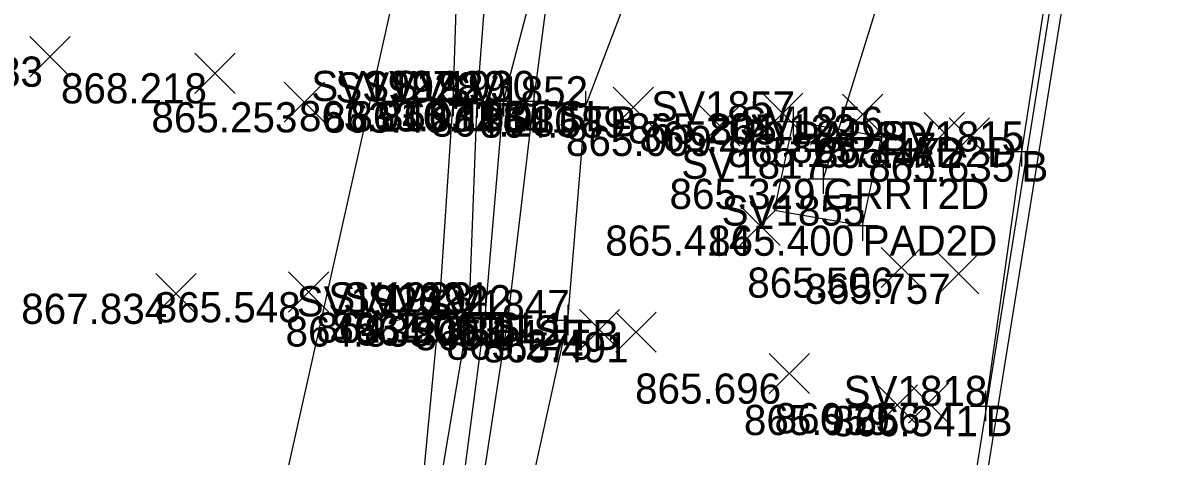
# Model space of a CAD drawing. Extents: x 2228183 to 2230895, y 679226 to 682223.
# Drawn here: x 2228233.78 to 2228271.79, y 680400.51 to 680414.86 of the extents above; entities that cross this region are included whole.
import ezdxf

# ---------------------------------------------------------------- set-up
doc = ezdxf.new("R2010")
doc.units = 0
for name, color, linetype in [('DR_X_Ditch', 7, 'Continuous'), ('PV_X_EOP', 7, 'Continuous'), ('PV_X_Shoulder_Aggregate', 7, 'Continuous'), ('RD_X_Concrete_Pad', 7, 'Continuous'), ('RD_X_GR_Rt', 7, 'Continuous'), ('SC_Scratch1', 7, 'Continuous'), ('SV_P_Control_Cells_Set', 7, 'Continuous'), ('SV_X_Break_Lines', 7, 'Continuous'), ('SV_X_Random_Point', 7, 'Continuous'), ('SV_X_Shot_Marker', 7, 'Continuous'), ('SV_X_Text_Comment', 7, 'Continuous'), ('SV_X_Toe_of_Slope', 7, 'Continuous'), ('SV_X_Top_of_Bank', 7, 'Continuous'), ('VG_X_Tree_Line_Rt', 7, 'Continuous')]:
    doc.layers.add(name, color=color, linetype=linetype)

msp = doc.modelspace()

# ---------------------------------------------------------------- linework, layer by layer
at = {"layer": 'DR_X_Ditch'}
msp.add_lwpolyline([(2228248.152, 680398.096), (2228249.095, 680405.268), (2228249.691, 680412.267), (2228250.738, 680416.294), (2228251.182, 680418.776), (2228251.754, 680424.586), (2228252.425, 680433.411), (2228253.413, 680441.336), (2228254.696, 680448.568), (2228253.869, 680453.653), (2228253.021, 680456.333), (2228253.924, 680458.912), (2228254.395, 680462.481), (2228255.204, 680465.484), (2228255.304, 680468.353), (2228255.892, 680471.795), (2228254.699, 680480.343), (2228253.82, 680482.578)], dxfattribs=at)
at = {"layer": 'PV_X_EOP'}
msp.add_lwpolyline([(2228252.395, 680193.158), (2228252.017, 680217.928), (2228252.166, 680243.969), (2228252.969, 680269.118), (2228254.41, 680295.326), (2228256.289, 680320.959), (2228258.609, 680345.957), (2228261.353, 680370.084), (2228265.081, 680396.038), (2228268.964, 680420.227), (2228273.571, 680445.935), (2228278.026, 680470.103), (2228282.912, 680494.405), (2228287.764, 680519.213), (2228292.491, 680542.983), (2228297.123, 680567.244), (2228301.725, 680591.365), (2228306.593, 680616.395), (2228311.35, 680641.501), (2228316.271, 680666.166), (2228321.17, 680690.642)], dxfattribs=at)
at = {"layer": 'PV_X_Shoulder_Aggregate'}
msp.add_lwpolyline([(2228251.688, 680193.163), (2228251.4, 680217.895), (2228251.524, 680243.996), (2228252.468, 680269.192), (2228253.879, 680295.388), (2228256.006, 680320.988), (2228258.289, 680346.01), (2228261.054, 680370.168), (2228264.719, 680396.078), (2228268.579, 680420.338), (2228273.034, 680446.093), (2228277.679, 680470.182), (2228282.388, 680494.533), (2228287.18, 680519.364), (2228291.91, 680543.114), (2228296.422, 680567.366), (2228298.906, 680579.954), (2228299.502, 680580.4), (2228300.213, 680585.238), (2228301.248, 680591.351), (2228306.286, 680616.474), (2228310.79, 680641.597), (2228315.628, 680666.277), (2228320.418, 680690.758)], dxfattribs=at)
at = {"layer": 'RD_X_Concrete_Pad'}
for p, q in [((2228259.272, 680411.599), (2228258.643, 680408.663)), ((2228258.643, 680408.663), (2228261.577, 680408.149))]:
    msp.add_line(p, q, dxfattribs=at)
msp.add_lwpolyline([(2228261.577, 680408.149), (2228262.206, 680411.085), (2228259.272, 680411.599)], dxfattribs=at)
at = {"layer": 'RD_X_GR_Rt'}
msp.add_lwpolyline([(2228317.277, 680691.491), (2228312.595, 680666.948), (2228307.846, 680642.212), (2228302.988, 680616.983), (2228299.878, 680601.719), (2228297.761, 680591.905), (2228295.954, 680582.306), (2228293.417, 680567.926), (2228288.785, 680543.533), (2228284.091, 680519.921), (2228279.274, 680495.191), (2228277.122, 680484.488), (2228274.573, 680472.619), (2228272.345, 680459.942), (2228269.701, 680446.744), (2228267.226, 680435.025), (2228263.818, 680421.121), (2228260.268, 680409.699)], dxfattribs=at)
at = {"layer": 'SV_X_Break_Lines'}
msp.add_lwpolyline([(2228320.273, 680690.8), (2228315.504, 680666.348), (2228310.738, 680641.634), (2228307.941, 680626.405), (2228307.393, 680623.472), (2228306.032, 680616.453), (2228303.053, 680601.155), (2228302.136, 680596.655), (2228301.06, 680591.437), (2228300.056, 680585.377), (2228299.678, 680583.167), (2228299.406, 680580.537), (2228298.77, 680580.019), (2228296.305, 680567.394), (2228291.772, 680543.248), (2228287.045, 680519.362), (2228285.465, 680511.012), (2228284.573, 680506.414), (2228282.283, 680494.649), (2228277.562, 680470.257), (2228272.956, 680446.158), (2228268.352, 680420.353), (2228266.832, 680410.603), (2228265.647, 680402.172)], dxfattribs=at)
at = {"layer": 'SV_X_Random_Point'}
for p, q in [((2228234.002, 680413.082), (2228235.336, 680414.417)), ((2228234.002, 680414.417), (2228235.336, 680413.082)), ((2228239.469, 680412.529), (2228240.803, 680413.864)), ((2228239.469, 680413.864), (2228240.803, 680412.529)), ((2228242.427, 680411.57), (2228243.761, 680412.905)), ((2228242.427, 680412.905), (2228243.761, 680411.57)), ((2228253.323, 680411.395), (2228254.657, 680412.73)), ((2228253.323, 680412.73), (2228254.657, 680411.395)), ((2228258.261, 680411.202), (2228259.595, 680412.537)), ((2228258.261, 680412.537), (2228259.595, 680411.202)), ((2228260.911, 680411.17), (2228262.245, 680412.505)), ((2228260.911, 680412.505), (2228262.245, 680411.17)), ((2228256.172, 680410.788), (2228257.506, 680412.123)), ((2228256.172, 680412.123), (2228257.506, 680410.788)), ((2228263.614, 680410.559), (2228264.948, 680411.894)), ((2228263.614, 680411.894), (2228264.948, 680410.559)), ((2228264.44, 680410.389), (2228265.774, 680411.724)), ((2228264.44, 680411.724), (2228265.774, 680410.389)), ((2228257.512, 680407.485), (2228258.846, 680408.82)), ((2228257.512, 680408.82), (2228258.846, 680407.485)), ((2228262.195, 680406.093), (2228263.529, 680407.428)), ((2228262.195, 680407.428), (2228263.529, 680406.093)), ((2228264.086, 680405.889), (2228265.42, 680407.224)), ((2228264.086, 680407.224), (2228265.42, 680405.889)), ((2228238.175, 680405.226), (2228239.509, 680406.561)), ((2228238.175, 680406.561), (2228239.509, 680405.226)), ((2228242.571, 680405.277), (2228243.905, 680406.612)), ((2228242.571, 680406.612), (2228243.905, 680405.277)), ((2228252.199, 680404.037), (2228253.533, 680405.372)), ((2228252.199, 680405.372), (2228253.533, 680404.037)), ((2228253.41, 680403.951), (2228254.744, 680405.286)), ((2228253.41, 680405.286), (2228254.744, 680403.951)), ((2228258.481, 680402.582), (2228259.815, 680403.917)), ((2228258.481, 680403.917), (2228259.815, 680402.582)), ((2228262.063, 680401.542), (2228263.397, 680402.877)), ((2228262.063, 680402.877), (2228263.397, 680401.542)), ((2228263.099, 680401.602), (2228264.433, 680402.937)), ((2228263.099, 680402.937), (2228264.433, 680401.602))]:
    msp.add_line(p, q, dxfattribs=at)
at = {"layer": 'SV_X_Shot_Marker'}
for p, q in [((2228248.019, 680412.774), (2228248.019, 680411.774)), ((2228248.818, 680412.727), (2228248.818, 680411.727)), ((2228249.691, 680412.767), (2228249.691, 680411.767)), ((2228250.692, 680412.774), (2228250.692, 680411.774)), ((2228252.399, 680412.597), (2228252.399, 680411.597)), ((2228247.519, 680412.274), (2228248.519, 680412.274)), ((2228248.019, 680412.274), (2228248.019, 680412.274)), ((2228248.318, 680412.227), (2228249.318, 680412.227)), ((2228248.818, 680412.227), (2228248.818, 680412.227)), ((2228249.191, 680412.267), (2228250.191, 680412.267)), ((2228249.691, 680412.267), (2228249.691, 680412.267)), ((2228250.192, 680412.274), (2228251.192, 680412.274)), ((2228250.692, 680412.274), (2228250.692, 680412.274)), ((2228251.899, 680412.097), (2228252.899, 680412.097)), ((2228252.399, 680412.097), (2228252.399, 680412.097)), ((2228259.272, 680412.099), (2228259.272, 680411.099)), ((2228258.772, 680411.599), (2228259.772, 680411.599)), ((2228259.272, 680411.599), (2228259.272, 680411.599)), ((2228262.206, 680411.585), (2228262.206, 680410.585)), ((2228261.706, 680411.085), (2228262.706, 680411.085)), ((2228262.206, 680411.085), (2228262.206, 680411.085)), ((2228266.832, 680411.103), (2228266.832, 680410.103)), ((2228266.332, 680410.603), (2228267.332, 680410.603)), ((2228266.832, 680410.603), (2228266.832, 680410.603)), ((2228260.268, 680410.199), (2228260.268, 680409.199)), ((2228259.768, 680409.699), (2228260.768, 680409.699)), ((2228260.268, 680409.699), (2228260.268, 680409.699)), ((2228261.577, 680408.649), (2228261.577, 680407.649)), ((2228261.077, 680408.149), (2228262.077, 680408.149)), ((2228261.577, 680408.149), (2228261.577, 680408.149)), ((2228247.542, 680405.642), (2228247.542, 680404.642)), ((2228248.549, 680405.769), (2228248.549, 680404.769)), ((2228249.095, 680405.768), (2228249.095, 680404.768)), ((2228249.858, 680405.677), (2228249.858, 680404.677)), ((2228248.049, 680405.269), (2228249.049, 680405.269)), ((2228248.549, 680405.269), (2228248.549, 680405.269)), ((2228248.595, 680405.268), (2228249.595, 680405.268)), ((2228249.095, 680405.268), (2228249.095, 680405.268)), ((2228251.813, 680405.52), (2228251.813, 680404.52)), ((2228247.042, 680405.142), (2228248.042, 680405.142)), ((2228247.542, 680405.142), (2228247.542, 680405.142)), ((2228249.358, 680405.177), (2228250.358, 680405.177)), ((2228249.858, 680405.177), (2228249.858, 680405.177)), ((2228251.313, 680405.02), (2228252.313, 680405.02)), ((2228251.813, 680405.02), (2228251.813, 680405.02)), ((2228265.647, 680402.672), (2228265.647, 680401.672)), ((2228265.147, 680402.172), (2228266.147, 680402.172)), ((2228265.647, 680402.172), (2228265.647, 680402.172))]:
    msp.add_line(p, q, dxfattribs=at)
at = {"layer": 'SV_X_Toe_of_Slope'}
for points in [[(2228247.363, 680398.195), (2228248.549, 680405.269), (2228248.818, 680412.227), (2228249.327, 680418.887), (2228250.556, 680424.555), (2228251.157, 680433.567), (2228252.542, 680441.162), (2228253.839, 680448.589), (2228253.231, 680453.1), (2228252.107, 680454.105), (2228250.987, 680456.203), (2228252.313, 680459.504), (2228253.331, 680462.687), (2228254.374, 680464.819), (2228254.89, 680468.476), (2228255.601, 680471.521), (2228254.065, 680480.323), (2228253.345, 680482.191)], [(2228248.769, 680398.124), (2228249.858, 680405.177), (2228250.692, 680412.274), (2228251.23, 680416.422), (2228252.326, 680418.965), (2228253.526, 680423.926), (2228253.811, 680432.797), (2228253.924, 680435.141), (2228254.135, 680441.28), (2228255.741, 680448.336), (2228254.458, 680453.857), (2228254.543, 680454.732), (2228254.934, 680456.198), (2228255.832, 680458.437), (2228255.885, 680462.309), (2228256.037, 680464.674), (2228255.856, 680468.365), (2228256.292, 680472.05), (2228254.247, 680482.064)]]:
    msp.add_lwpolyline(points, dxfattribs=at)
at = {"layer": 'SV_X_Top_of_Bank'}
for points in [[(2228250.307, 680398.124), (2228251.813, 680405.02), (2228252.399, 680412.097), (2228254.905, 680418.699), (2228255.946, 680423.789), (2228256.296, 680434.591), (2228257.527, 680440.797), (2228257.898, 680448.164), (2228256.801, 680454.49), (2228258.019, 680458.203), (2228257.686, 680462.292), (2228256.963, 680468.691), (2228257.054, 680472.414), (2228255.862, 680480.443), (2228255.026, 680481.727), (2228254.275, 680482.126)], [(2228246.89, 680398.302), (2228247.542, 680405.142), (2228248.019, 680412.274), (2228248.247, 680419.019), (2228247.645, 680424.706), (2228248.424, 680434.173), (2228248.473, 680441.514)]]:
    msp.add_lwpolyline(points, dxfattribs=at)
at = {"layer": 'VG_X_Tree_Line_Rt'}
msp.add_lwpolyline([(2228242.224, 680398.608), (2228254.757, 680454.617), (2228285.377, 680608.953), (2228295.459, 680686.843), (2228290.96, 680699.609), (2228297.38, 680721.363), (2228313.146, 680792.869)], dxfattribs=at)

# ---------------------------------------------------------------- texts
at = {"layer": 'SC_Scratch1'}
for s, p in [('869.183', (2228229.605, 680412.749)), ('868.218', (2228235.036, 680412.196)), ('865.253', (2228238.03, 680411.237)), ('863.916', (2228242.915, 680411.274)), ('863.407', (2228243.722, 680411.227)), ('863.032', (2228244.618, 680411.267)), ('863.193', (2228245.628, 680411.274)), ('864.280', (2228247.285, 680411.097)), ('864.589', (2228248.906, 680411.062)), ('865.204', (2228253.806, 680410.869)), ('865.122', (2228256.505, 680410.837)), ('865.009', (2228251.755, 680410.455)), ('865.219', (2228254.188, 680410.599)), ('865.157', (2228257.11, 680410.085)), ('865.217', (2228259.185, 680410.226)), ('865.472', (2228260.034, 680410.056)), ('865.635', (2228261.762, 680409.603)), ('865.329', (2228255.184, 680408.699)), ('865.414', (2228253.057, 680407.152)), ('865.400', (2228256.463, 680407.149)), ('865.506', (2228257.758, 680405.76)), ('865.757', (2228259.657, 680405.556)), ('867.834', (2228233.72, 680404.893)), ('865.548', (2228238.138, 680404.944)), ('864.113', (2228243.485, 680404.269)), ('863.906', (2228243.991, 680404.268)), ('864.835', (2228242.472, 680404.142)), ('864.003', (2228244.794, 680404.177)), ('865.042', (2228246.74, 680404.02)), ('865.275', (2228247.796, 680403.704)), ('865.491', (2228248.995, 680403.618)), ('865.696', (2228254.044, 680402.249)), ('865.959', (2228257.646, 680401.209)), ('866.256', (2228258.662, 680401.269)), ('866.341', (2228260.565, 680401.172))]:
    msp.add_text(s, height=1, dxfattribs=at).set_placement(p)
at = {"layer": 'SV_P_Control_Cells_Set'}
for s, p in [('SV1927', (2228243.325, 680412.274)), ('SV1928', (2228244.119, 680412.227)), ('SV1929', (2228245.009, 680412.267)), ('SV1930', (2228245.98, 680412.274)), ('SV1852', (2228247.728, 680412.097)), ('SV1857', (2228254.578, 680411.599)), ('SV1856', (2228257.504, 680411.085)), ('SV1815', (2228262.163, 680410.603)), ('SV1817', (2228255.574, 680409.699)), ('SV1855', (2228256.908, 680408.149)), ('SV1926', (2228242.84, 680405.142)), ('SV1923', (2228243.887, 680405.269)), ('SV1924', (2228244.375, 680405.268)), ('SV1922', (2228245.187, 680405.177)), ('SV1847', (2228247.119, 680405.02)), ('SV1818', (2228260.948, 680402.172))]:
    msp.add_text(s, height=1, dxfattribs=at).set_placement(p)
at = {"layer": 'SV_X_Text_Comment'}
for s, p in [('TB1', (2228248.019, 680411.274)), ('TSL1', (2228248.818, 680411.227)), ('D', (2228249.691, 680411.267)), ('TSL', (2228250.692, 680411.274)), ('TB', (2228252.399, 680411.097)), ('PAD2D', (2228259.272, 680410.599)), ('PAD2D', (2228262.206, 680410.085)), ('B', (2228266.832, 680409.603)), ('GRRT2D', (2228260.268, 680408.699)), ('PAD2D', (2228261.577, 680407.149)), ('TSL1', (2228248.549, 680404.269)), ('D', (2228249.095, 680404.268)), ('TB1', (2228247.542, 680404.142)), ('TSL', (2228249.858, 680404.177)), ('TB', (2228251.813, 680404.02)), ('B', (2228265.647, 680401.172))]:
    msp.add_text(s, height=1, dxfattribs=at).set_placement(p)

doc.saveas('drawing.dxf')
